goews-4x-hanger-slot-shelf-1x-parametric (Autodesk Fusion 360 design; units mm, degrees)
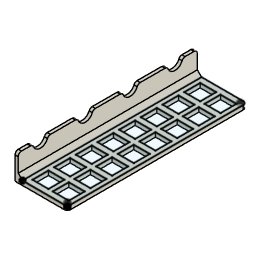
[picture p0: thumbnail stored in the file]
parameter "SlotWidth" = 15
parameter "SlotDepth" = 15
base_feature "Base Feature" bodies "Quad Plate Blank"
work_plane "WorkPlane1" AlongDistance 4
delete_face "DeleteFace1"
sketch "Sketch1" plane through (0, 0, -108.1504) normal (0, 0, 1) x axis (-1, 0, 0)
  line L1 (-103.15, 20.8) -> (-103.15, -146.8)
  line L2 (-142.15, 20.8) -> (-103.15, 20.8)
  line L3 (-145.15, -143.8) -> (-145.15, 17.8)
  line L4 (-103.15, -146.8) -> (-142.15, -146.8)
  line L5 (-126.15, 15.5111) -> (-141.15, 15.5111)
  line L6 (-126.15, 0.5111) -> (-126.15, 15.5111)
  line L7 (-141.15, 0.5111) -> (-126.15, 0.5111)
  line L8 (-141.15, 15.5111) -> (-141.15, 0.5111)
  line L9 (-107.15, 0.5111) -> (-107.15, 15.5111)
  line L10 (-122.15, 0.5111) -> (-107.15, 0.5111)
  line L11 (-107.15, 15.5111) -> (-122.15, 15.5111)
  line L12 (-122.15, 15.5111) -> (-122.15, 0.5111)
  line L13 (-126.15, -19.7778) -> (-126.15, -4.7778)
  line L14 (-141.15, -19.7778) -> (-126.15, -19.7778)
  line L15 (-126.15, -4.7778) -> (-141.15, -4.7778)
  line L16 (-141.15, -4.7778) -> (-141.15, -19.7778)
  line L17 (-107.15, -19.7778) -> (-107.15, -4.7778)
  line L18 (-122.15, -19.7778) -> (-107.15, -19.7778)
  line L19 (-107.15, -4.7778) -> (-122.15, -4.7778)
  line L20 (-122.15, -4.7778) -> (-122.15, -19.7778)
  line L21 (-126.15, -40.0667) -> (-126.15, -25.0667)
  line L22 (-141.15, -40.0667) -> (-126.15, -40.0667)
  line L23 (-126.15, -25.0667) -> (-141.15, -25.0667)
  line L24 (-141.15, -25.0667) -> (-141.15, -40.0667)
  line L25 (-107.15, -40.0667) -> (-107.15, -25.0667)
  line L26 (-122.15, -40.0667) -> (-107.15, -40.0667)
  line L27 (-107.15, -25.0667) -> (-122.15, -25.0667)
  line L28 (-122.15, -25.0667) -> (-122.15, -40.0667)
  line L29 (-142.15, 20.8) -> (-103.15, 20.8)
  line L30 (-145.15, -143.8) -> (-145.15, 17.8)
  line L31 (-103.15, -146.8) -> (-142.15, -146.8)
  line L32 (-103.15, 20.8) -> (-103.15, -146.8)
  line L33 (-126.15, -60.3556) -> (-126.15, -45.3556)
  line L34 (-141.15, -60.3556) -> (-126.15, -60.3556)
  line L35 (-126.15, -45.3556) -> (-141.15, -45.3556)
  line L36 (-141.15, -45.3556) -> (-141.15, -60.3556)
  line L37 (-107.15, -60.3556) -> (-107.15, -45.3556)
  line L38 (-122.15, -60.3556) -> (-107.15, -60.3556)
  line L39 (-107.15, -45.3556) -> (-122.15, -45.3556)
  line L40 (-122.15, -45.3556) -> (-122.15, -60.3556)
  line L41 (-126.15, -80.6444) -> (-126.15, -65.6444)
  line L42 (-141.15, -80.6444) -> (-126.15, -80.6444)
  line L43 (-126.15, -65.6444) -> (-141.15, -65.6444)
  line L44 (-141.15, -65.6444) -> (-141.15, -80.6444)
  line L45 (-107.15, -80.6444) -> (-107.15, -65.6444)
  line L46 (-122.15, -80.6444) -> (-107.15, -80.6444)
  line L47 (-107.15, -65.6444) -> (-122.15, -65.6444)
  line L48 (-122.15, -65.6444) -> (-122.15, -80.6444)
  line L49 (-126.15, -100.9333) -> (-126.15, -85.9333)
  line L50 (-141.15, -100.9333) -> (-126.15, -100.9333)
  line L51 (-126.15, -85.9333) -> (-141.15, -85.9333)
  line L52 (-141.15, -85.9333) -> (-141.15, -100.9333)
  line L53 (-107.15, -100.9333) -> (-107.15, -85.9333)
  line L54 (-122.15, -100.9333) -> (-107.15, -100.9333)
  line L55 (-107.15, -85.9333) -> (-122.15, -85.9333)
  line L56 (-122.15, -85.9333) -> (-122.15, -100.9333)
  line L57 (-126.15, -121.2222) -> (-126.15, -106.2222)
  line L58 (-141.15, -121.2222) -> (-126.15, -121.2222)
  line L59 (-126.15, -106.2222) -> (-141.15, -106.2222)
  line L60 (-141.15, -106.2222) -> (-141.15, -121.2222)
  line L61 (-107.15, -121.2222) -> (-107.15, -106.2222)
  line L62 (-122.15, -121.2222) -> (-107.15, -121.2222)
  line L63 (-107.15, -106.2222) -> (-122.15, -106.2222)
  line L64 (-122.15, -106.2222) -> (-122.15, -121.2222)
  line L65 (-126.15, -141.5111) -> (-126.15, -126.5111)
  line L66 (-141.15, -141.5111) -> (-126.15, -141.5111)
  line L67 (-126.15, -126.5111) -> (-141.15, -126.5111)
  line L68 (-141.15, -126.5111) -> (-141.15, -141.5111)
  line L69 (-107.15, -141.5111) -> (-107.15, -126.5111)
  line L70 (-122.15, -141.5111) -> (-107.15, -141.5111)
  line L71 (-107.15, -126.5111) -> (-122.15, -126.5111)
  line L72 (-122.15, -126.5111) -> (-122.15, -141.5111)
  arc A1 centre (-142.15, 17.8) radius 3 clockwise from (-145.15, 17.8) to (-142.15, 20.8)
  arc A2 centre (-142.15, -143.8) radius 3 clockwise from (-142.15, -146.8) to (-145.15, -143.8)
  arc A3 centre (-142.15, -143.8) radius 3 clockwise from (-142.15, -146.8) to (-145.15, -143.8)
  arc A4 centre (-142.15, 17.8) radius 3 clockwise from (-145.15, 17.8) to (-142.15, 20.8)
  point P3 (-103.15, 20.8)
  point P34 (-103.15, 20.8)
  point P35 (-145.15, 20.8)
  point P4 (-142.15, 20.8)
  point P8 (-142.15, -146.8)
  point P10 (-141.15, 15.5111)
  point P11 (-126.15, 15.5111)
  point P13 (-141.15, 0.5111)
  point P36 (-103.15, -146.8)
  horizontal L5
  vertical L6
  horizontal L7
  vertical L8
  horizontal L29
  vertical L30
  horizontal L31
  vertical L32
  coincident P3 P34
  tangent L31 A3
  tangent L30 A3
  coincident P35 L29
  coincident P35 L30
  tangent L29 A4
  tangent L30 A4
  dimension "d10" distance P4 P8 = 167.6
  dimension "d11" distance P10 P11 = 15 (= "SlotDepth")
  dimension "d12" distance P10 P13 = 15 (= "SlotWidth")
  dimension "d13" distance L2 L5 = 5.2889 (= "( 167.6 mm - ( SlotWidth * SlotsWide ) ) / ( SlotsWide + 1 )")
  dimension "d18" distance L3 L8 = 4 (= "( 42 mm - ( SlotDepth * SlotsDeep ) ) / ( SlotsDeep + 1 )")
  dimension "d26" distance P34 P35 = 42
  dimension "d27" distance P34 P36 = 167.6
  dimension "d28" radius A3 = 3
  dimension "d29" radius A4 = 3
  dimension "d16" R-Pattern1-uDistance = 19 (= "SlotDepth + ( 42 mm - ( SlotDepth * SlotsDeep ) ) / ( SlotsDeep + 1 )")
  dimension "d17" R-Pattern1-vDistance = -20.2889 (= "-SlotWidth - ( ( 167.6 mm - ( SlotWidth * SlotsWide ) ) / ( SlotsWide + 1 ) )")
extrude "Extrude4" add sketch "Sketch1" against normal blind 4
named bodies: "Quad Plate Blank"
